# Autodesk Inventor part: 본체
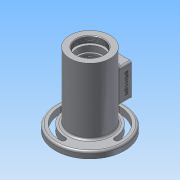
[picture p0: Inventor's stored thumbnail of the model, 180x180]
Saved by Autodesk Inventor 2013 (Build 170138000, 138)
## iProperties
Created: 2017-05
Part Number: 본체
Material: 알루미늄 6061
Document SubType Name: Modeling
Designer: Administrator
Density: 2.71 g/cm^3
Mass: 676.471 g
Surface Area: 616.844 cm^2
Volume: 249.62 cm^3
Author: Administrator
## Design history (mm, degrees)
sketch "스케치1"
  geometry: C1 r 53 at (0, 0); C2 r 31 at (0, 0); 1 further point
  constraints: 2 centre point, 2 coincident
  dimensions: "d0" = 106 diameter of C1; "d1" = 62 diameter of C2
extrude "돌출1" new body sketch "스케치1" distance "d2" = 10; taper "d3" = 0 deg
extrude "돌출2" join sketch "스케치1" distance "d4" = 3; taper "d5" = 0 deg
sketch "스케치2"
  geometry: C1 r 53 at (0, 0) reference; C2 r 31 at (0, 0)
  constraints: 1 centre point, 1 coincident
  dimensions: "d6" = 62 diameter of C2
extrude "돌출3" join sketch "스케치2" distance "d7" = 102; taper "d8" = 0 deg
sketch "스케치3"
  geometry: C1 r 22 at (0, 0); 1 further point
  constraints: 1 centre point, 1 coincident
  dimensions: "d9" = 44 diameter of C1
node "작업 평면1"
sketch "스케치4"
  geometry: C1 r 16 at (0, 0); 1 further point
  constraints: 1 centre point, 1 coincident
  dimensions: "d11" = 32 diameter of C1
feature "로프트1" sketch "스케치4" dims "d12" = 0, "d13" = 90 deg, "d14" = 0, "d15" = 90 deg
hole "구멍1" diameter "d18" = 20; stored, may be unused: countersink angle "d22" = 90 deg, drill point angle "d24" = 0 deg; dims "d19" = 6, "d20" = 25, "d21" = 7.3, "d23" = 8, "d73" = 10, "d74" = 10
hole "구멍2" diameter "d27" = 42; stored, may be unused: countersink angle "d31" = 90 deg, drill point angle "d33" = 0 deg; dims "d25" = 10, "d26" = 10, "d28" = 6, "d29" = 25, "d30" = 7.3, "d32" = 9
sketch "스케치5"
  geometry: L1 (-21, 112)-(21, 112) reference; L2 (22, -3)-(-22, -3) reference; L3 (0, 112)-(0, -3); L4 (21, 103)-(-21, 103) reference; L5 (0, 103)-(24, 103); L6 (24, 103)-(24, 100); L7 (24, 100)-(0, 100); L8 (0, 100)-(0, 103); 1 further point
  constraints: 10 end point, 3 midpoint, 2 parallel, 1 horizontal, 1 perpendicular
  dimensions: "d37" = 3 distance of L5.end L6.end; "d39" = 24 distance of L6.end L7.end
revolve "회전1" sketch "스케치5" stored, may be unused: angle "d40" = 90 deg
hole "구멍3" diameter "d43" = 35; stored, may be unused: countersink angle "d47" = 90 deg, drill point angle "d49" = 0 deg; dims "d44" = 6, "d45" = 40, "d46" = 9, "d48" = 74, "d123" = 10, "d124" = 10
sketch "스케치6"
  geometry: L1 (-21, 112)-(21, 112) reference; L2 (22, -3)-(-22, -3) reference; L3 (0, 112)-(0, -3); L4 (0, 87.75)-(18.5, 87.75); L5 (18.5, 87.75)-(18.5, 86); L6 (18.5, 86)-(0, 86); L7 (0, 87.75)-(0, 86); 1 further point
  constraints: 10 end point, 3 perpendicular, 2 midpoint, 2 point on line, 1 parallel
  dimensions: "d52" = 1.75 distance of L4.end L5.end; "d54" = 18.5 distance of L5.end L6.end; "d55" = 26 distance between parallel lines of L1 L6
revolve "회전2" sketch "스케치6" stored, may be unused: angle "d56" = 90 deg
sketch "스케치7"
  geometry: L1 (-21, 112)-(21, 112) reference; L2 (22, -3)-(-22, -3) reference; L3 (0, 112)-(0, -3); L4 (0, 75)-(26, 75); L5 (26, 75)-(26, 37); L6 (26, 37)-(0, 37); L7 (0, 75)-(0, 37); 1 further point
  constraints: 10 end point, 3 perpendicular, 2 midpoint, 2 point on line, 1 collinear
  dimensions: "d57" = 38 distance of L4.end L5.end; "d59" = 26 distance of L5.end L6.end; "d60" = 37 distance between parallel lines of L1 L4
revolve "회전3" sketch "스케치7" stored, may be unused: angle "d61" = 90 deg
hole "구멍4" diameter "d66" = 33; stored, may be unused: countersink angle "d70" = 90 deg, drill point angle "d72" = 0 deg; dims "d64" = 10, "d65" = 10, "d67" = 6, "d68" = 4, "d69" = 2, "d71" = 5
sketch "스케치8"
  geometry: 1 further point
fillet "모깎기1" dims "d112" = 3, "d113" = 0.3
node "작업 평면2"
sketch "스케치10"
  geometry: L1 (20, 81)-(-20, 81); L2 (-20, 81)-(-20, 31); L3 (-20, 31)-(20, 31); L4 (20, 31)-(20, 81); L5 (31, 112)-(-31, 112) reference; L6 (11, 72)-(-11, 72); L7 (-11, 72)-(-11, 40); L8 (-11, 40)-(11, 40); L9 (11, 40)-(11, 72); 2 further points
  constraints: 16 end point, 4 parallel, 2 perpendicular, 1 horizontal, 1 midpoint, 1 vertical alignment, 3 other
  dimensions: "d76" = 50 distance of L3.end L1.start; "d80" = 40 distance of L1.start L1.end; "d81" = 31 distance between parallel lines of L1 L5; "d82" = 32 distance of L6.end L7.end
extrude "돌출4" join sketch "스케치10" stored distance "d83" = 10; taper "d84" = 0 deg
extrude "돌출5" cut sketch "스케치10" distance "d85" = 40; taper "d86" = 0 deg
sketch "스케치11"
  geometry: L1 (11, -40)-(11, -72) reference; L2 (-11, -72)-(-11, -40) reference; L3 (-20, -81)-(20, -81) reference; L4 (20, -31)-(-20, -31) reference; L5 (-11, -56)-(11, -56); L6 (0, -81)-(0, -31); 5 further points
  constraints: 4 end point, 4 midpoint, 2 horizontal alignment, 2 vertical alignment
  dimensions: "d87" = 41 distance of point (-15.5, -35.5) point (-15.5, -76.5); "d89" = 20.5 distance from line of point (-15.5, -76.5) L5; "d90" = 31 distance of point (15.5, -76.5) point (-15.5, -76.5); "d91" = 15.5 distance from line of L6 point (15.5, -76.5)
hole "구멍5" sketch "스케치11" at (-15.5, -76.5), (-15.5, -35.5), (15.5, -35.5), (15.5, -76.5) diameter "d92" = 2.459; stored, may be unused: countersink angle "d96" = 90 deg, drill point angle "d98" = 118 deg; dims "d93" = 6, "d94" = 4, "d95" = 2, "d97" = 8
feature "스레드1" dims "d99" = 10, "d100" = 0
sketch "스케치12"
  geometry: L1 (0, 53)-(0, 0); L2 (0, 0)-(-53, 0); C1 r 31 at (0, 0) reference; A1 r 53 centre (0, 0) between (0, 53) and (-53, 0) reference; A2 r 45.5 centre (0, 0) between (0, 45.5) and (-45.5, 0); A3 r 37.5 centre (0, 0) between (0, 37.5) and (-37.5, 0); A4 r 4 centre (0, 41.5) between (0, 37.5) and (0, 45.5); A5 r 4 centre (-41.5, 0) between (-45.5, 0) and (-37.5, 0); A6 r 45.5 centre (0, 0) between (0, -45.5) and (45.5, 0); A7 r 37.5 centre (0, 0) between (0, -37.5) and (37.5, 0); A8 r 4 centre (41.5, 0) between (45.5, 0) and (37.5, 0); A9 r 4 centre (0, -41.5) between (0, -37.5) and (0, -45.5)
  constraints: 18 point on circle, 8 centre point, 8 tangent, 4 end point, 2 coincident, 2 horizontal alignment, 2 point on line, 1 perpendicular, 1 vertical, 1 vertical alignment
  dimensions: "d101" = 45.5 radius of A2; "d104" = 37.5 radius of A3; "d105" = 45.5 radius of A6; "d106" = 37.5 radius of A7
extrude "돌출6" cut sketch "스케치12" distance "d107" = 13; taper "d108" = 0 deg
chamfer "모따기1" distance "d109" = 1; stored, may be unused: second distance "d110" = 2, angle "d111" = 45 deg
fillet "모깎기2" dims "d114" = 3
sketch "스케치13"
  geometry: L1 (0, 0)-(44, 0) reference; L2 (-34, -13)-(-34, -75) reference; 2 further points
  constraints: 1 other
  dimensions: "d116" = 56 distance from line of L2 point (22, -8); "d117" = 8 distance from line of L1 point (22, -8)
feature "엠보싱1" sketch "스케치13" dims "d0" = 106, "d1" = 62, "d12" = 0, "d13" = 90 deg, "d14" = 0, "d15" = 90 deg, "d118" = 0.5, "d119" = 0
chamfer "모따기2" distance "d120" = 0.7; stored, may be unused: second distance "d121" = 2, angle "d122" = 30 deg
chamfer "모따기3" distance "d125" = 1; stored, may be unused: second distance "d126" = 2, angle "d127" = 45 deg
chamfer "모따기4" distance "d128" = 1; stored, may be unused: second distance "d129" = 2, angle "d130" = 45 deg
node "솔리드1"
other parameters: "d10" = -11, "d75" = 44
